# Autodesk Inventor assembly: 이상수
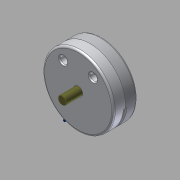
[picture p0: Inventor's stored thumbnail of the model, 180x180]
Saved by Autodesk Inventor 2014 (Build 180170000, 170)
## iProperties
Created: 2015-05
Part Number: 이상수
Document SubType Name: Assembly
Designer: USER
Author: USER
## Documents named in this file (10)
- C:\Users\USER\Desktop\Inventor2급\이상수.iam
- C:\Users\USER\Desktop\Inventor2급\이상수.ipt
- C:\Users\USER\Desktop\Inventor2급\20150513-2급공용부품\M 10 x 35.ipt
- C:\Users\USER\Desktop\Inventor2급\20150513-2급공용부품\덮개.ipt
- C:\Users\USER\Desktop\Inventor2급\20150513-2급공용부품\멈춤링.ipt
- C:\Users\USER\Desktop\Inventor2급\20150513-2급공용부품\베어링62_22.ipt
- C:\Users\USER\Desktop\Inventor2급\20150513-2급공용부품\슬라이더.ipt
- C:\Users\USER\Desktop\Inventor2급\20150513-2급공용부품\슬라이더2.ipt
- C:\Users\USER\Desktop\Inventor2급\20150513-2급공용부품\축.ipt
- C:\Users\USER\Desktop\Inventor2급\20150513-2급공용부품\평행핀.ipt
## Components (2 placed, 1 different names)
1. M 10 x 35:1
2. M 10 x 35:3
